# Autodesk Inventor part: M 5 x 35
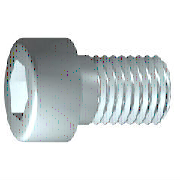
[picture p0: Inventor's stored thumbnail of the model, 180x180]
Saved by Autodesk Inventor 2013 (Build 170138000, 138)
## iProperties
IsCustomPart: 0
Company: 한국ATC센터
Created: 2014-12
Part Number: M 5 x 35
Material: 강, 연강
Description: 6각머리 태핑 나사
Document SubType Name: Modeling
Standard: KS B 1003
Designer: KYOUNG IL JANG
Standards Organization: KS
Language: ko-KR
Size Designation: M 5 x 35
Categories: <MemberInstance><Categories><Category DisplayName="조임쇠" InternalName="e4da775c-781d-43d5-af7c-5136215cf5a6" Mnemonic="FSTN"><Category DisplayName="볼트" InternalN
Density: 7.86 g/cm^3
Mass: 7.27786 g
Surface Area: 8.23857 cm^2
Volume: 0.925936 cm^3
Author: KYOUNG IL JANG
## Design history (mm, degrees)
sketch "스케치1"
  geometry: L1 (-1.167, 0)-(35, 0); L2 (35, 0)-(35, 2.5); L3 (35, 2.5)-(13, 2.5); L4 (13, 2.5)-(12.509, 2.5); L5 (12.509, 2.5)-(0, 2.5); L6 (0, 2.5)-(0, 4.25); L7 (0, 4.25)-(-5, 4.25); L8 (-5, 4.25)-(-5, 2.309); L9 (-5, 2.309)-(-2.5, 2.309); L10 (-2.5, 2.309)-(-1.167, 0); L11 (-13, 0)-(43, 0) reference; L12 (0, -0.85)-(0, 5.1) reference; L13 (13, 2.5)-(0, 2.5)
  constraints: 22 end point, 6 parallel, 2 collinear, 2 perpendicular, 1 horizontal, 1 point on line
  dimensions: "d1" = 22 distance from line of L3.end L2 (= GEL); "d2" = 0.49086 distance of L4.end L3.end (computed from GAL); "d3" = 5 distance between parallel lines of L8 L6 (= KOH); "d4" = 2.5 distance of L8.end L9.end (= INTI); "d5" = 60 deg angle of L10 L1; "d6" = 5 diameter of L3 L1 (= GD); "d7" = 5 diameter of L5 L1 (= BDM); "d8" = 4.6188 diameter of L9 L1 (= 1.1547 x SW); "d9" = 8.5 diameter of L7 L1 (= KOD); "d26" = 35 distance between parallel lines of L12 L2 (= NLG)
revolve "본체" sketch "스케치1" stored, may be unused: angle "d10" = 90 deg
sketch "스케치2"
  geometry: L1 (0, -5.95)-(0, 5.95) reference; L2 (-5.95, 0)-(5.95, 0) reference; L3 (2.309, 0)-(1.155, -2); L4 (1.155, -2)-(-1.155, -2); L5 (-1.155, -2)-(-2.309, 0); L6 (-2.309, 0)-(-1.155, 2); L7 (-1.155, 2)-(1.155, 2); L8 (1.155, 2)-(2.309, 0); 2 further points
  constraints: 12 end point, 1 coincident, 1 horizontal alignment, 1 point on line, 12 other
extrude "슬롯" join sketch "스케치2" stored distance "d11" = 10; taper "d12" = 0 deg
workplane "Work Plane1"
fillet "Fillet2" dims "d30" = 0.1 (= R)
body "Solid1"
fillet "모깎기1" dims "d17" = 0.5 (= RR)
feature "스레드" dims "d13" = 22 (= GEL), "d14" = 0
chamfer "모따기1" distance "d15" = 0.49076 (= -0.5 x SPD + 0.5 x GD); stored, may be unused: second distance "d16" = 0.49076 (= GUL), angle "d27" = 45 deg
other parameters: "GD" = 5 (= NND) [user parameter; used in 2 equation terms], "NLG" = 35 [user parameter; used in 1 equation term], "GEL" = 22 [user parameter; used in 2 equation terms], "KOD" = 8.5 [user parameter; used in 1 equation term], "KOH" = 5 [user parameter; used in 1 equation term], "INTI" = 2.5 [user parameter; used in 1 equation term], "GAL" = 0.49076 (= 0.61345 x PTC) [user parameter; used in 1 equation term], "GUL" = 0.49076 (= 0.61345 x PTC) [user parameter; used in 1 equation term], "BDM" = 5 (= NND) [user parameter; used in 1 equation term], "SW" = 4 [user parameter; used in 2 equation terms], "RR" = 0.5 [user parameter; used in 1 equation term], "SPD" = 4.01848 (= NND - 1.2269 x PTC) [user parameter; used in 1 equation term], "d19" = 0, "d28" = 0, "d29" = 0, "R" = 0.1 [user parameter; used in 1 equation term], "PHH" = 0.2 [user parameter], "GD1" = 4.01848 (= THREADDIA - 1.2269 x PTC) [user parameter], "THREADDIA" = 5 [user parameter; used in 1 equation term], "FAWI" = 45 deg [user parameter], "TPU" = 12.5 (computed from PTC) [user parameter], "PTC" = 0.8 [user parameter; used in 5 equation terms], "NND" = 5 [user parameter; used in 3 equation terms], "TOA" = 30 deg [user parameter], "E0" = 4.62 (= 1.155 x SW) [user parameter]
